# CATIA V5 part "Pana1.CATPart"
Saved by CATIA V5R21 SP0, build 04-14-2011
Part number: Pana1
Bounding box of the stored display mesh (mm): x -1.15 to 1.15, y 1.5 to 4, z 12.35 to 19.65
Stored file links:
  C:\Users\MIRCEA\Desktop\PRRO\CATIAV5\Pana1.CATPart
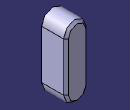
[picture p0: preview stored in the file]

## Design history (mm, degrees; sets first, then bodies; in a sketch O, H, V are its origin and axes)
Body1 (main body)
  Plane1: type Offset, RefPlane zx-plane, Offset 4
  Sketch1 on Plane1, origin (0, 4, 0), H (-1, 0, 0), V (0, 0, 1)
    construction line L1 (0, 18.5) -> (0, 13.5)
    line L2 (1.15, 18.5) -> (1.15, 13.5)
    line L3 (-1.15, 13.5) -> (-1.15, 18.5)
    arc A1 centre (0, 13.5) radius 1.15 from (1.15, 13.5) to (-1.15, 13.5) cw
    arc A2 centre (0, 18.5) radius 1.15 from (-1.15, 18.5) to (1.15, 18.5) cw
    length L1 = 5
    distance L1 L2 = 1.15
    vertical: L1 V
    tangency: A1 L2, A2 L2, A1 L3, A2 L3
  Pad1: profile Sketch1, direction (0, -1, 0), length 2.5
  Chamfer1: length 0.25, angle 45, on edge [face of Pad1 from Sketch1.A2 | start face of Pad1]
